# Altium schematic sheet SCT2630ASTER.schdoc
size 127 x 101 mm
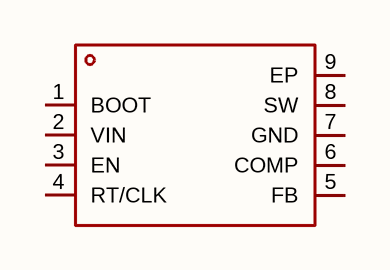
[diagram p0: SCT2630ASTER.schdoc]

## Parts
U?  sct2630aster  [ESOP-8_L4.9-W3.9-P1.27-LS6.0-BL-EP]  (value not drawn)

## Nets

Not connected (* = marked no-connect by the designer): U? 1(BOOT) 2(VIN) 3(EN) 4(RT/CLK) 5(FB) 6(COMP) 7(GND) 8(SW) 9(EP)

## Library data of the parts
U? = sct2630aster: 功能类型:降压型;工作电压:4.5V~60V;输出电压:800mV~57V;输出电流:3.5A;输出类型:可调;; Manufacturer: SCT(芯洲科技); AddInBom: yes; ModelId: d3e00daa36c445139c055a3b9efb85d2; ModelName: ESOP-8_L4.9-W3.9-H1.6-LS6.0-P1.27; ModelTransform: 240.157,192.913,0,90,0,0,0,0,0; Function: 降压型; Output Current: 3.5A; Frequency - Switching: 1.2MHz; Synchronous Rectifier: 否; Number of Outputs: 1; Topology: 降压式; Quiescent Current: 175uA; Switch tube (built-in/external): 内置; Output Type: 可调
